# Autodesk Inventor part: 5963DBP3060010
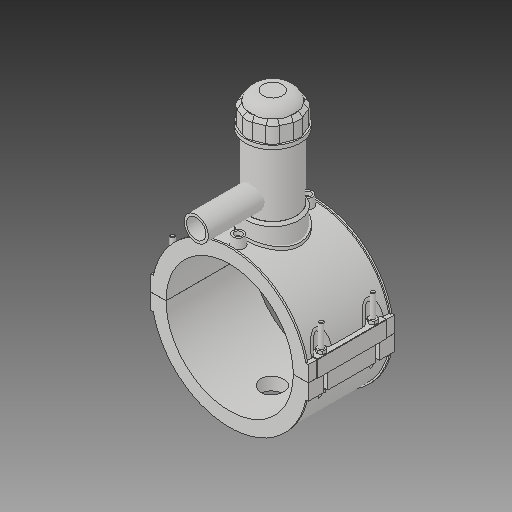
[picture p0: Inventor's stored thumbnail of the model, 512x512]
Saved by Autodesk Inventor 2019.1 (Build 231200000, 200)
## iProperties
Created: 2017-07
Part Number: 5963DBP3060010
Material: Generic
Description: PLASSON TAPPING SADDLE 6''DIPS x 1''IPS
Document SubType Name: Modeling
Designer: KIM
Density: 1 g/cm^3
Appearance: Default
Author: KIM
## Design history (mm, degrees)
derived "5963DBP_5963BUP.ipt"
feature "Solid1::5963DBP_5963BUP.ipt"
feature "Solid2::5963DBP_5963BUP.ipt"
feature "Solid3::5963DBP_5963BUP.ipt"
tag "TaggingFeature1"
body "Solid1"
body "Solid2"
body "Solid3"
other parameters: "d0" = 174.5, "d2" = 215.9, "d3" = 43.625, "d4" = 118.11, "d5" = 0, "d6" = 0.1, "d8" = 0, "d19" = 6, "d20" = 6, "d21" = 70.866, "d23" = 0, "d24" = 35.433, "d26" = 0, "d27" = 3, "d28" = 3, "d29" = 3, "d30" = 58.16667, "d31" = 6, "d32" = 0, "d33" = 0, "d34" = 0.6, "d40" = 108.888, "d41" = 75.035, "d43" = 0, "d45" = 0, "d47" = 175.566, "d70" = 15, "d72" = 0, "d73" = 6, "d75" = 5, "d76" = 0, "d77" = 8.725, "d78" = 117.25, "d79" = 15, "d80" = 47.244, "d82" = 5 deg, "d84" = 4, "d85" = 14, "d86" = 0, "d87" = 3, "d88" = 0, "d89" = 1, "d90" = 1, "d91" = 94.488, "d92" = 0, "d93" = 0.5, "d94" = 91.84211, "d96" = 213.588, "d97" = 2.3622, "d98" = 0, "d120" = 140 deg, "d121" = 24.228, "d122" = 20 deg, "d123" = 418.8, "d124" = 125.64, "d126" = 0, "d143" = 179.735, "d145" = 26.84615, "d149" = 2.6175, "d150" = 29.53077, "d153" = 118.11, "d154" = 0, "d156" = 104.7, "d157" = 160 deg, "d159" = 6.98, "d161" = 2.6175, "d162" = 70.866, "d163" = 0, "d164" = 87.25, "d167" = 17.45, "d168" = 102.14634, "d170" = 3.4335, "d172" = 0, "d173" = 1, "d175" = 87.25, "d176" = 20 deg, "d177" = 12.215, "d178" = 34.9, "d180" = 0, "d183" = 13.96, "d184" = 9.772, "d185" = 38.38575, "d186" = 38.38575, "d187" = 104.7, "d188" = 10.47, "d189" = 12.215, "d190" = 0, "d191" = 157.05, "d193" = 7.3248, "d194" = 4.13385, "d195" = 90 deg, "d197" = 0, "d199" = 0, "d200" = 17.45, "d202" = 0, "d203" = 177.038, "d204" = 71.28325, "d205" = 52.5245, "d206" = 63.77975, "d207" = 132.7785, "d208" = 138.08964, "d209" = 164.64534, "d210" = 64.5301, "d211" = 75.035, "d212" = 60.028, "d213" = 43.5366, "d216" = 0, "d217" = 17.45, "d218" = 17.45, "d219" = 3.49, "d222" = 174.5, "d224" = 0, "d225" = 65.024, "d226" = 33.3, "d227" = 26.64, "d228" = 104.902, "d230" = 5.235, "d_" = 174.5, "B_" = 215.9, "L_" = 118.11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
